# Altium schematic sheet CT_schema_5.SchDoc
size 208 x 258 mm
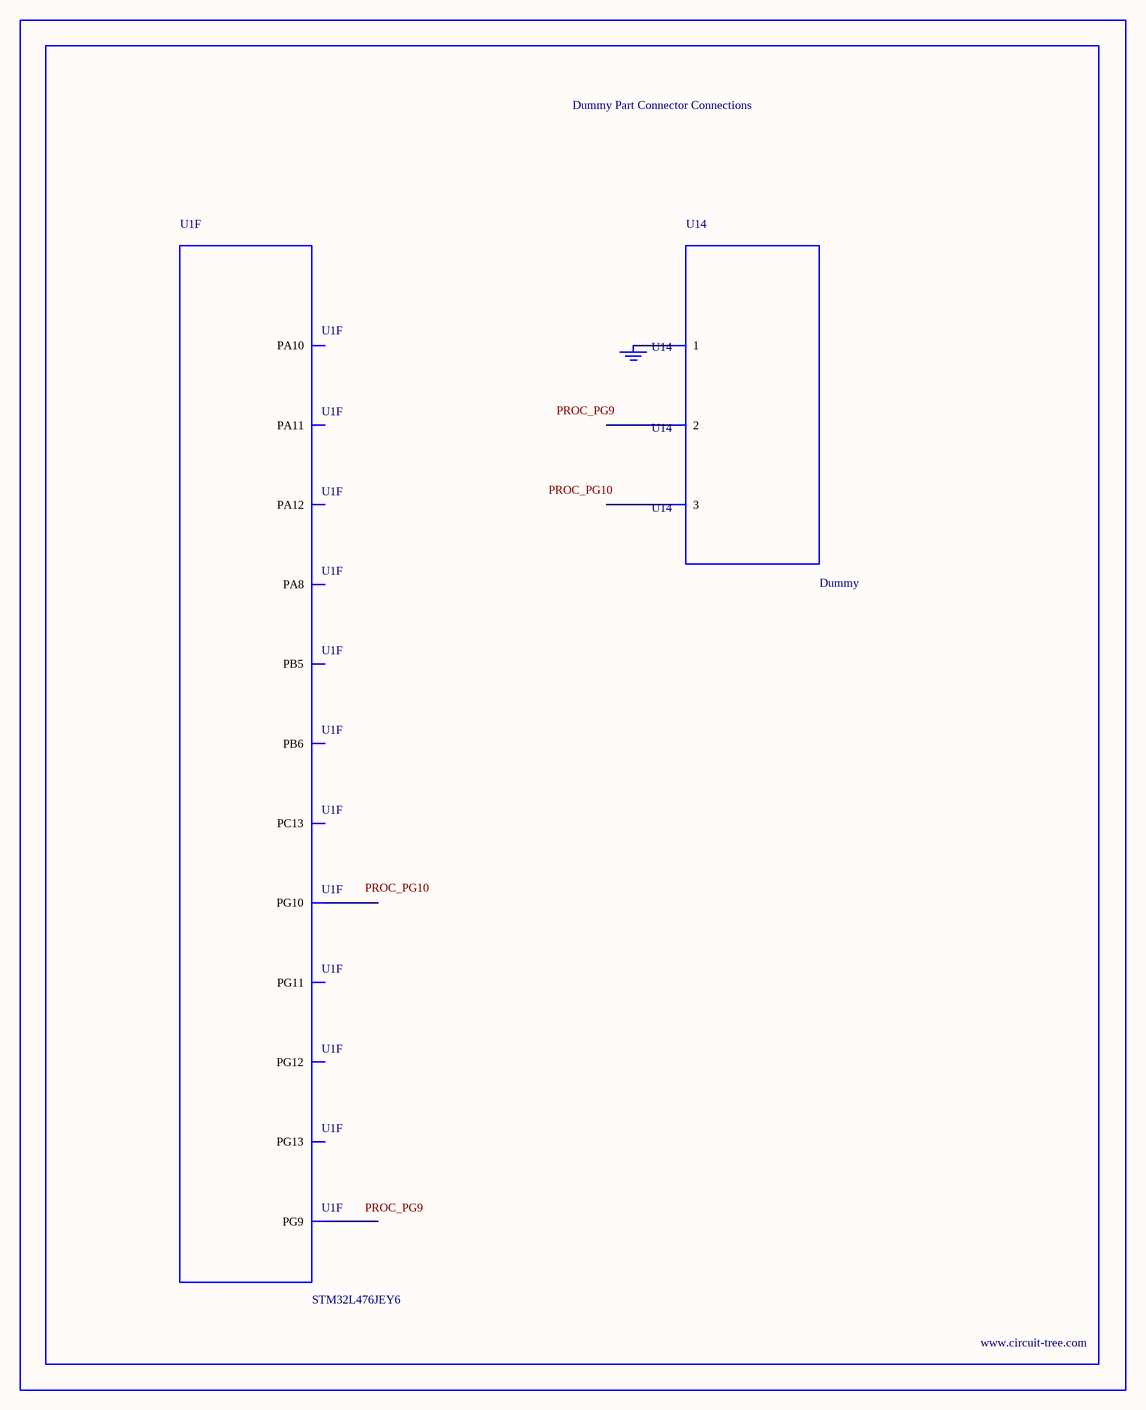
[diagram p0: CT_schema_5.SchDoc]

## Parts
BORDER4  (no value)
GND_INSTANCE_4_0  (no value)
U1  STM32L476JEY6  [WLCSP72]  (part F of 6)
U14  Dummy  [DUMMY_PACKAGE_186]

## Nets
NetGND_INSTANCE_4_0_0: GND_INSTANCE_4_0.0(GND) U14.1

Not connected (* = marked no-connect by the designer): U1 A4(PG9) B4(PG10) B5(PG13) B7(PB6) B8(PC13) C1(PA12) C4(PG11) C5(PG12) C7(PB5) D1(PA11) D2(PA10) E2(PA8); U14 2 3

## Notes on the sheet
- Labels drawn without touching a wire or pin: PROC_PG9, PROC_PG10

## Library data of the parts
BORDER4 = BORDER_PAGE4
GND_INSTANCE_4_0 = GND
